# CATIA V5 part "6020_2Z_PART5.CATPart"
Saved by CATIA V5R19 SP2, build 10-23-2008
Part number: 6020_2Z_PART5
Bounding box of the stored display mesh (mm): x 4.46 to 19.54, y 55.159 to 69.841, z -7.241 to 7.241
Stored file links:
  G:\EU_thinkMotion\CFAO_2010\MMS_groupe2\MMS_groupe2\OK\nrosalie\nrosalie_cfao_support_d_arme_legere_final\6020_2Z_PART5.CATPart
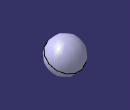
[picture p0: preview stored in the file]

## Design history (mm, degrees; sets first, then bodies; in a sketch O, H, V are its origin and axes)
Set1
  Point1: (0, 0, 0)
  Point2: (1, 0, 0)
  Point3: (0, 1, 0)
  Plane1: type 3Points, Element1 Point1, Element2 Point2, Element3 Point3
Body1 (main body)
  Sketch1 on Plane1, origin (0, 0, 0), H (1, 0, 0), V (0, 1, 0)
    arc A1 centre (12, 62.5) radius 7.54 from (19.54, 62.5) to (4.46, 62.5) ccw
    point P1 (19.54, 62.5)
    point P2 (4.46, 62.5)
    line L1 (19.54, 62.5) -> (4.46, 62.5)
    point P3 (19.54, 62.5)
    point P4 (4.46, 62.5)
    axis line L2 (19.54, 62.5) -> (4.46, 62.5)
    point P5 (19.54, 62.5)
    point P6 (4.46, 62.5)
    point P7 (19.54, 62.5)
    point P8 (4.46, 62.5)
    coincidence: P5 P7, P6 P8
  Shaft1: profile Sketch1, axis Sketch1.L2, angle 360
